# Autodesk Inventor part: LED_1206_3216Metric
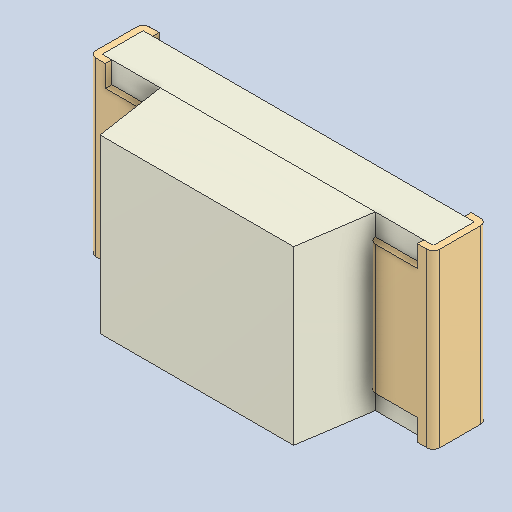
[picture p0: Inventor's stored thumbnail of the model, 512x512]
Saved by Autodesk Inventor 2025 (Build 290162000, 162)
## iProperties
Created: 2026-09
Part Number: LED_1206_3216Metric
Material: Generic
Document SubType Name: Modeling
Designer: Leonardo
Density: 1 g/cm^3
Appearance: Default
Author: Leonardo
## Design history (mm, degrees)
feature "Base1"
body "Solid1"
